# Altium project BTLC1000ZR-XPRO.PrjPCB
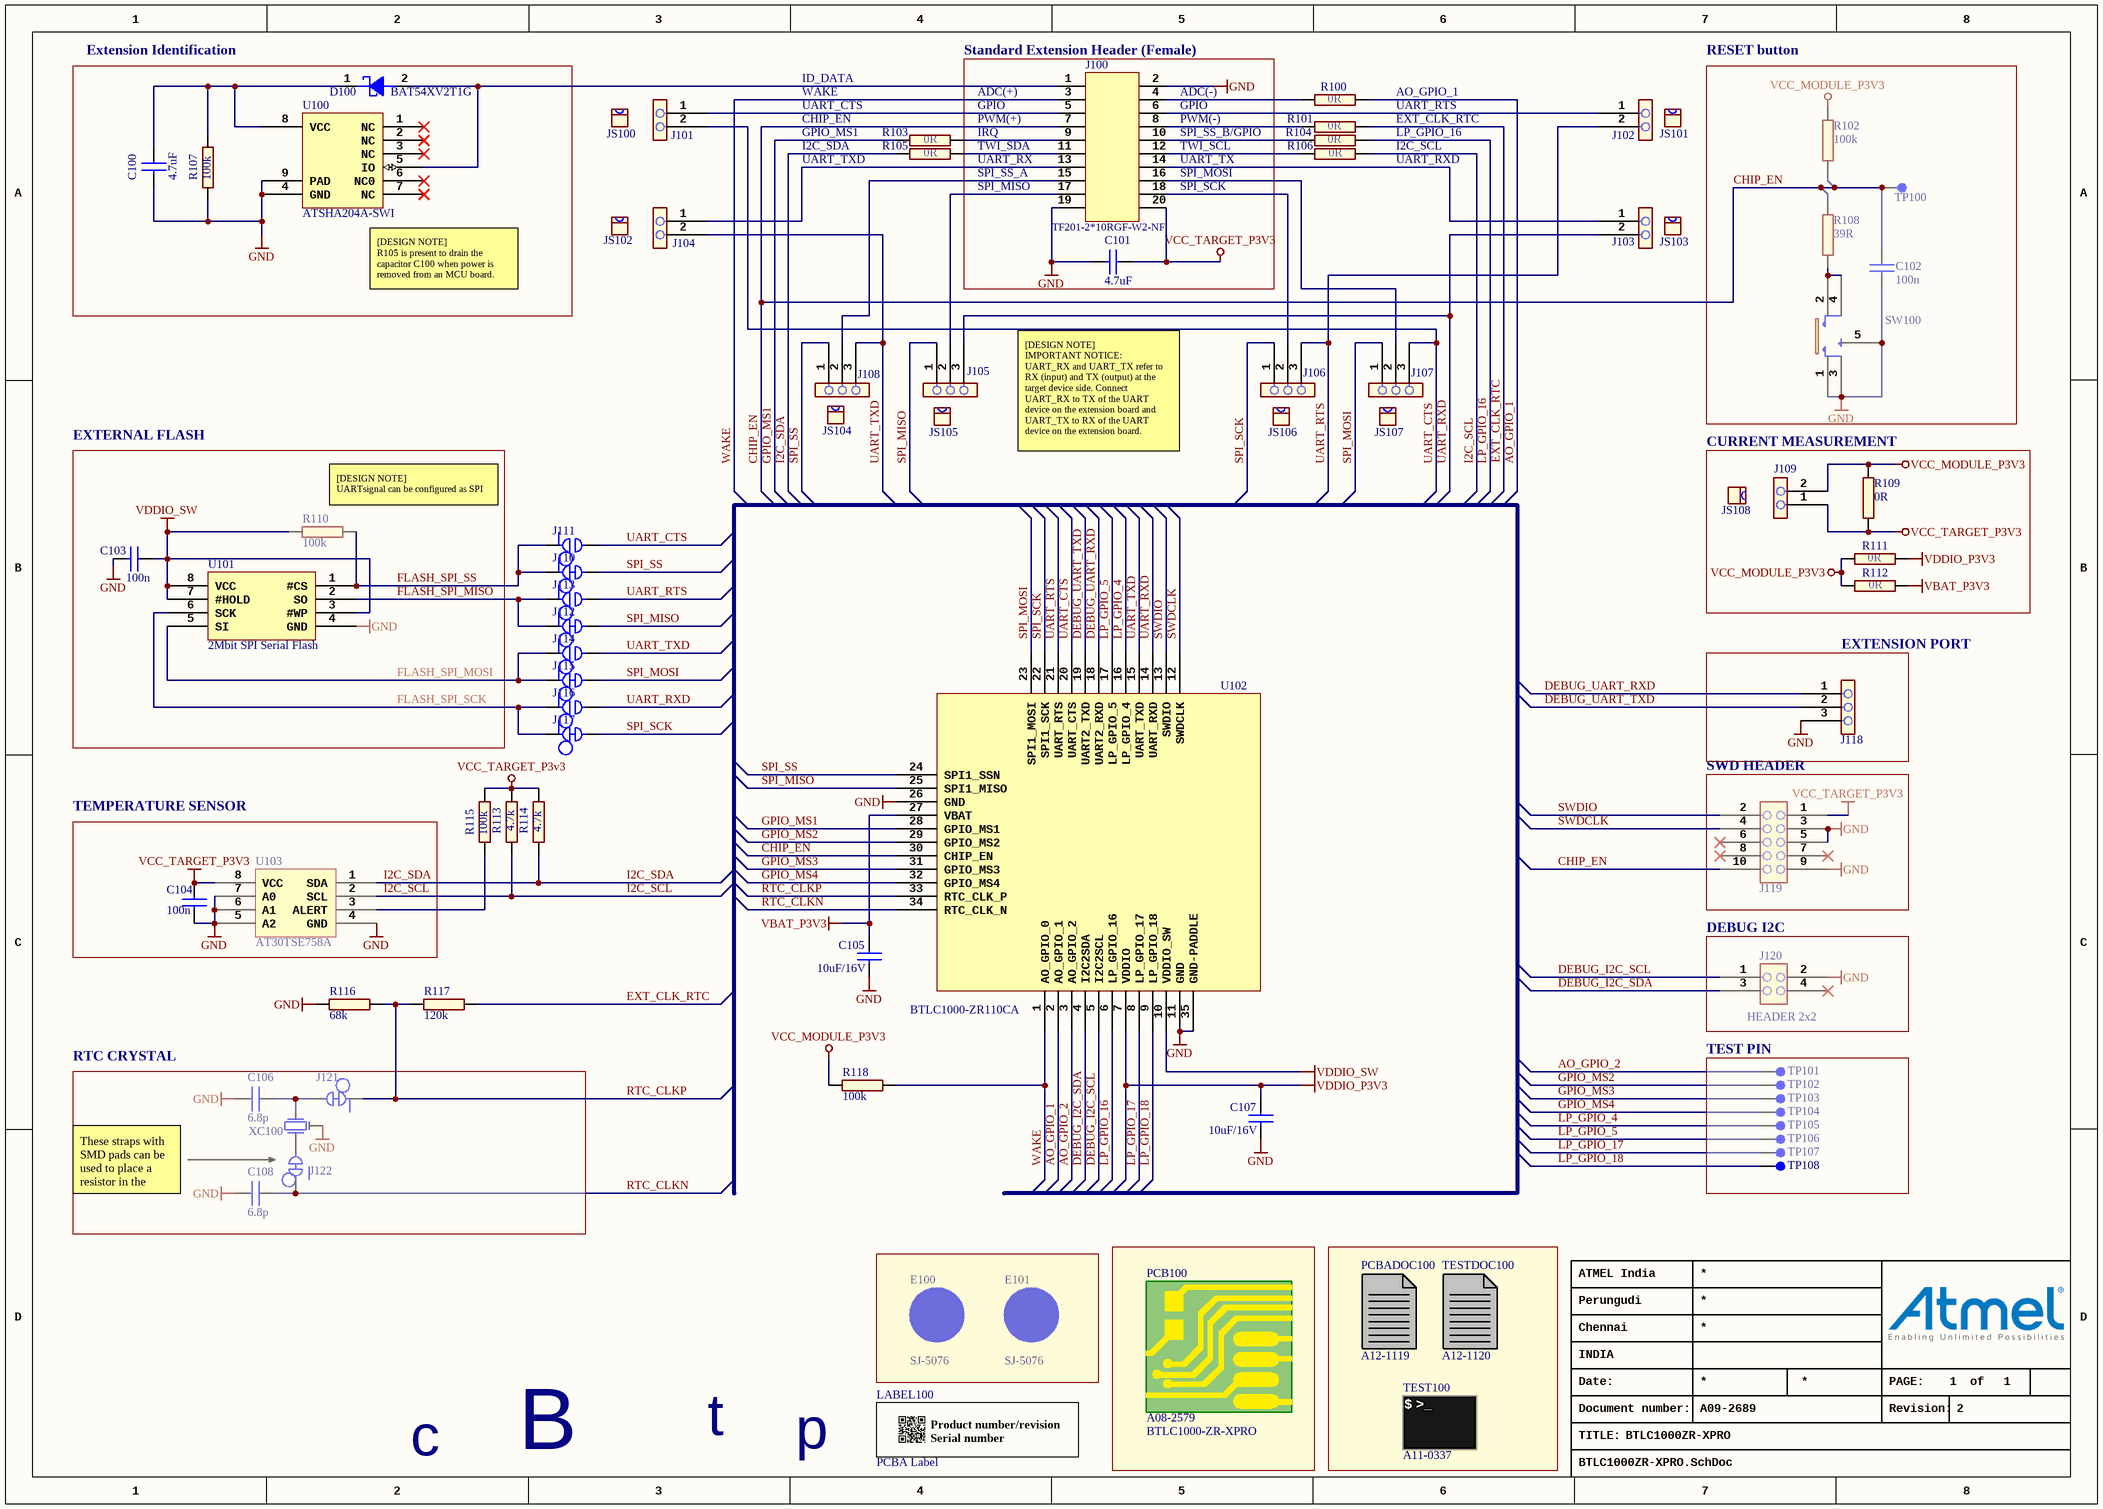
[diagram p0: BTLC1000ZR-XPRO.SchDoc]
1 sheet, 83 parts. Net scope: global (net labels, ports and power ports of the same name join across sheets).
Board file: BTLC1000ZR-XPRO.PcbDoc

## Sheet BTLC1000ZR-XPRO.SchDoc: BTLC1000ZR-XPRO
size A3; Organization: ATMEL India; Address1: Perungudi; Address2: Chennai; Address3: INDIA; DocumentNumber: A09-2689; Revision: 2; SheetNumber: 1; SheetTotal: 1; PageSetup: Record=PageOptions¦CenterHorizontal=True¦CenterVertical=True¦PrintScale=0.68¦XCorrection=1.00¦YCorrection=1.00¦PrintKind=1¦BorderSize=5000000¦LeftOffset=0¦BottomOffset=0¦Orientation=2¦PaperLength=1000¦PaperWidth=1000¦Scale=100¦PaperSource=7¦PrintQuality=-4¦MediaType=1¦DitherType=10¦PaperKind=A3 (297 x 420 mm)¦PrintScaleMode=1

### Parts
C100  value 4.7uF  [AP1-00001]  (hidden comment: Recommended by Escatec. No datasheet available yet.)
C101  value 4.7uF  [AP1-00001]  (hidden comment: Recommended by Escatec. No datasheet available yet.)
C102  100n  [AP1-00053]
C103  value 100n  [AP1-00001]  (hidden comment: CAP-NONPOL)
C104  value 100n  [AP1-00001]  (hidden comment: CAP-NONPOL)
C105  value 10uF/16V  [AP1-00039]  (hidden comment: Close to Pin22(VDDIO)of U101)
C106  value 6.8p  [AP1-00001]  (hidden comment: CAP-NONPOL)
C107  value 10uF/16V  [AP1-00039]  (hidden comment: Close to Pin22(VDDIO)of U101)
C108  value 6.8p  [AP1-00001]  (hidden comment: CAP-NONPOL)
D100  value BAT54XV2T1G  [AP4-00036]  (hidden comment: Farnell# 1615809)
E100  value SJ-5076  [AP8-00192]
E101  value SJ-5076  [AP8-00192]
J100  value TF201-2*10RGF-W2-NF  [AP8-00621]
J101  (no value)  [AP8-00733]
J102  (no value)  [AP8-00733]
J103  (no value)  [AP8-00733]
J104  (no value)  [AP8-00733]
J105  Same as A08-1614 but with 1mm hole for optimal reflow soldering (no misalignment of the component)  [AP8-00745]  (value not drawn)
J106  Same as A08-1614 but with 1mm hole for optimal reflow soldering (no misalignment of the component)  [AP8-00745]  (value not drawn)
J107  Same as A08-1614 but with 1mm hole for optimal reflow soldering (no misalignment of the component)  [AP8-00745]  (value not drawn)
J108  Same as A08-1614 but with 1mm hole for optimal reflow soldering (no misalignment of the component)  [AP8-00745]  (value not drawn)
J109  (no value)  [AP8-00733]
J110  SMD-STRAP_CLOSED  [AP8-00595]  (value not drawn)  (net tie, no BOM)
J111  SMD-STRAP_OPEN  [AP8-00596]  (value not drawn)  (no BOM)
J112  SMD-STRAP_CLOSED  [AP8-00595]  (value not drawn)  (net tie, no BOM)
J113  SMD-STRAP_OPEN  [AP8-00596]  (value not drawn)  (no BOM)
J114  SMD-STRAP_OPEN  [AP8-00596]  (value not drawn)  (no BOM)
J115  SMD-STRAP_CLOSED  [AP8-00595]  (value not drawn)  (net tie, no BOM)
J116  SMD-STRAP_OPEN  [AP8-00596]  (value not drawn)  (no BOM)
J117  SMD-STRAP_CLOSED  [AP8-00595]  (value not drawn)  (net tie, no BOM)
J118  Same as A08-1614 but with 1mm hole for optimal reflow soldering (no misalignment of the component)  [AP8-00745]  (value not drawn)
J119  HEADER 2x5  [AP8-00257]  (value not drawn)
J120  HEADER 2x2  [AP8-00179]
J121  (no value)  [AP9-00044]  (net tie, no BOM)
J122  (no value)  [AP9-00044]  (net tie, no BOM)
JS100  To be used by request from ESCATEC  [AP8-00525]  (value not drawn)
JS101  To be used by request from ESCATEC  [AP8-00525]  (value not drawn)
JS102  To be used by request from ESCATEC  [AP8-00525]  (value not drawn)
JS103  To be used by request from ESCATEC  [AP8-00525]  (value not drawn)
JS104  To be used by request from ESCATEC  [AP8-00525]  (value not drawn)
JS105  To be used by request from ESCATEC  [AP8-00525]  (value not drawn)
JS106  To be used by request from ESCATEC  [AP8-00525]  (value not drawn)
JS107  To be used by request from ESCATEC  [AP8-00525]  (value not drawn)
JS108  To be used by request from ESCATEC  [AP8-00525]  (value not drawn)
LABEL100  value PCBA Label  [AP8-00317]
PCB100  value BTLC1000-ZR-XPRO  AN: A08-2579  (hidden comment: PCB)  (mechanical)
PCBADOC100  AN: A12-1119  (hidden comment: PCBADOC)  (mechanical)
R100  value 0R  [AP2-00001]  (hidden comment: R2)
R101  value 0R  [AP2-00001]  (hidden comment: R2)
R102  value 100k  [AP2-00000]  (hidden comment: R2)
R103  value 0R  [AP2-00001]  (hidden comment: R2)
R104  value 0R  [AP2-00001]  (hidden comment: R2)
R105  value 0R  [AP2-00001]  (hidden comment: R2)
R106  value 0R  [AP2-00001]  (hidden comment: R2)
R107  value 100k  [AP2-00000]
R108  value 39R  [AP2-00000]  (hidden comment: R2)
R109  value 0R  [AP2-00001]  (hidden comment: R2)
R110  value 100k  [AP2-00000]  (hidden comment: R2)
R111  value 0R  [AP2-00001]  (hidden comment: R2)
R112  value 0R  [AP2-00001]  (hidden comment: R2)
R113  value 4.7k  [AP2-00000]  (hidden comment: R2)
R114  value 4.7k  [AP2-00000]  (hidden comment: R2)
R115  value 100k  [AP2-00000]  (hidden comment: R2)
R116  value 68k  [AP2-00001]  (hidden comment: R2)
R117  value 120k  [AP2-00001]  (hidden comment: R2)
R118  value 100k  [AP2-00001]  (hidden comment: R2)
SW100  PUSHBUTTON2  [AP8-00274]  (value not drawn)
TEST100  AN: A11-0337  (hidden comment: TEST)  (mechanical)
TESTDOC100  AN: A12-1120  (hidden comment: TESTDOC)  (mechanical)
TP100  TESTPOINT  [AP8-00010]  (value not drawn)  (no BOM)
TP101  TESTPOINT  [AP8-00256]  (value not drawn)  (no BOM)
TP102  TESTPOINT  [AP8-00256]  (value not drawn)  (no BOM)
TP103  TESTPOINT  [AP8-00256]  (value not drawn)  (no BOM)
TP104  TESTPOINT  [AP8-00256]  (value not drawn)  (no BOM)
TP105  TESTPOINT  [AP8-00256]  (value not drawn)  (no BOM)
TP106  TESTPOINT  [AP8-00256]  (value not drawn)  (no BOM)
TP107  TESTPOINT  [AP8-00256]  (value not drawn)  (no BOM)
TP108  TESTPOINT  [AP8-00256]  (value not drawn)  (no BOM)
U100  ATSHA204A-SWI  [AP6-00409]
U101  value 2Mbit SPI Serial Flash  [AP6-00000]  (hidden comment: IS25LD020-JNLE)
U102  value BTLC1000-ZR110CA  [AP9-00156]  (hidden comment: BTLC1000-ZR-XPRO)
U103  value AT30TSE758A  [AP6-00186]  (hidden comment: AT30TSx75x)
XC100  Farnell order no:1539364  [AP7-00044]  (value not drawn)

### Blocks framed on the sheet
Extension Identification: C100 D100 R107 U100
Standard Extension Header (Female): C101 J100
RESET button: C102 R102 R108 SW100 TP100
EXTERNAL FLASH: C103 R110 U101
CURRENT MEASUREMENT: J109 JS108 R109 R111 R112
EXTENSION PORT: J118
SWD HEADER: J119
TEMPERATURE SENSOR: C104 U103
DEBUG I2C: J120
RTC CRYSTAL: C106 C108 J121 J122 XC100
TEST PIN: TP101-TP108

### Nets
GND: C100.2 C101.2 C102.2 C103.2 C104.2 C105.2 C106.2 C107.2 C108.2 J100.2 J100.19 J118.3 J119.3 J119.5 J119.9 J120.2 R107.1 R116.1 SW100.1 SW100.3 SW100.5(GND) U100.4(GND) U100.9(PAD) U101.4(GND) U102.11(GND) U102.26(GND) U102.35(GND-PADDLE) U103.4(GND) U103.5(A2) U103.6(A1) U103.7(A0) U103.9(GND) XC100.3
VBAT_P3V3: C105.1 R112.1 U102.27(VBAT)
VCC_MODULE_P3V3: J109.2 R102.1 R109.2 R111.2 R112.2 R118.1
VCC_TARGET_P3V3: C101.1 C104.1 J100.20 J109.1 J119.1 R109.1 R113.1 R114.2 R115.1 U103.8(VCC)
VDDIO_P3V3: C107.1 R111.1 U102.7(VDDIO)
VDDIO_SW: C103.1 R110.2 U101.3(#WP) U101.7(#HOLD) U101.8(VCC) U102.10(VDDIO_SW)
AO_GPIO_1: R100.2 U102.2(AO_GPIO_1)
AO_GPIO_2: TP101.1 U102.3(AO_GPIO_2)
CHIP_EN: C102.1 J100.7 J119.10 R102.2 R108.1 TP100.1 U102.30(CHIP_EN)
DEBUG_I2C_SCL: J120.1 U102.5(I2C2SCL)
DEBUG_I2C_SDA: J120.3 U102.4(I2C2SDA)
DEBUG_UART_RXD: J118.1 U102.18(UART2_RXD)
DEBUG_UART_TXD: J118.2 U102.19(UART2_TXD)
EXT_CLK_RTC: R101.2 R117.2
FLASH_SPI_MISO: J112.1 J113.1 U101.2(SO)
FLASH_SPI_MOSI: J114.1 J115.1 U101.5(SI)
FLASH_SPI_SCK: J116.1 J117.1 U101.6(SCK)
FLASH_SPI_SS: J110.1 J111.1 R110.1 U101.1(#CS)
GPIO_MS1: R103.1 U102.28(GPIO_MS1)
GPIO_MS2: TP102.1 U102.29(GPIO_MS2)
GPIO_MS3: TP103.1 U102.31(GPIO_MS3)
GPIO_MS4: TP104.1 U102.32(GPIO_MS4)
I2C_SCL: R106.2 R113.2 U103.2(SCL)
I2C_SDA: R105.1 R114.1 U103.1(SDA)
LP_GPIO_4: TP105.1 U102.16(LP_GPIO_4)
LP_GPIO_5: TP106.1 U102.17(LP_GPIO_5)
LP_GPIO_16: R104.2 U102.6(LP_GPIO_16)
LP_GPIO_17: TP107.1 U102.8(LP_GPIO_17)
LP_GPIO_18: TP108.1 U102.9(LP_GPIO_18)
RTC_CLKN: C108.1 J122.1 U102.34(RTC_CLK_N)
RTC_CLKP: J121.1 R116.2 R117.1 U102.33(RTC_CLK_P)
SPI_MISO: J105.1 J112.2 U102.25(SPI1_MISO)
SPI_MOSI: J107.1 J115.2 U102.23(SPI1_MOSI)
SPI_SCK: J106.1 J117.2 U102.22(SPI1_SCK)
SPI_SS: J108.1 J110.2 U102.24(SPI1_SSN)
SWDCLK: J119.4 U102.12(SWDCLK)
SWDIO: J119.2 U102.13(SWDIO)
UART_CTS: J101.2 J107.3 J111.2 U102.20(UART_CTS)
UART_RTS: J102.2 J106.3 J113.2 U102.21(UART_RTS)
UART_RXD: J103.2 J105.3 J116.2 U102.14(UART_RXD)
UART_TXD: J104.2 J108.3 J114.2 U102.15(UART_TXD)
WAKE: J100.3 R118.2 U102.1(AO_GPIO_0)
NetC100_1: C100.1 D100.1(CATHODE) R107.2 U100.8(VCC)
NetC106_1: C106.1 J121.2 XC100.2
NetD100_2: D100.2(ANODE) J100.1 U100.5(IO)
NetJ100_4: J100.4 R100.1
NetJ100_5: J100.5 J101.1
NetJ100_6: J100.6 J102.1
NetJ100_8: J100.8 R101.1
NetJ100_9: J100.9 R103.2
NetJ100_10: J100.10 R104.1
NetJ100_11: J100.11 R105.2
NetJ100_12: J100.12 R106.1
NetJ100_13: J100.13 J104.1
NetJ100_14: J100.14 J103.1
NetJ100_15: J100.15 J108.2
NetJ100_16: J100.16 J107.2
NetJ100_17: J100.17 J105.2
NetJ100_18: J100.18 J106.2
NetJ122_2: J122.2 XC100.1
NetR108_2: R108.2 SW100.2 SW100.4
NetR115_2: R115.2 U103.3(ALERT)

Not connected (* = marked no-connect by the designer): E100 1(FIDUCIAL); E101 1(FIDUCIAL); J119 6* 7* 8*; J120 4*; U100 1(NC)* 2(NC)* 3(NC)* 6(NC0)* 7(NC)*

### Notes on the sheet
- ID_DATA
- WAKE
- UART_CTS
- ADC(+)
- GPIO
- (near J100) GPIO
- (near J100) ADC(-)
- AO_GPIO_1
- UART_RTS
- CHIP_EN
- GPIO_MS1
- I2C_SDA
- UART_TXD
- TWI_SDA
- UART_RX
- SPI_SS_A
- IRQ
- PWM(+)
- (near J100) PWM(-)
- (near J100) TWI_SCL
- (near J100) UART_TX
- (near J100) SPI_MOSI
- SPI_SS_B/GPIO
- EXT_CLK_RTC
- LP_GPIO_16
- I2C_SCL
- UART_RXD
- SPI_MISO
- (near J100) SPI_SCK
- (near U100) [DESIGN NOTE]
  R105 is present to drain the capacitor C100 when power is removed from an MCU board.
- [DESIGN NOTE]
  IMPORTANT NOTICE:
  UART_RX and UART_TX refer to RX (input) and TX (output) at the target device side. Connect UART_RX to TX of the UART device on the extension board and UART_TX to RX of the UART device on the extension board.
- (near R110) [DESIGN NOTE]
  UARTsignal can be configured as SPI
- These straps with SMD pads can be used to place a resistor in the XOUT signal in order to measure the oscillator allowance.
  By default these straps are closed and nothing is mounted on the pads.
- t
- p
- c
- B

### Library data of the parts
C100 C101 = A01-0347: Ceramic capacitor, SMD 0402, X5R, 6.3V, +/-20% (de33687); PartGroup: Capacitors,Ceramic,SMD 0402; Manufacturer: Murata; MPN: GRM155R60J475ME87D; Tolerance: +-20%; TemperatureRange: -55°C to +85°C; ComponentStatus: 'Active (verified)'
C102-C104 = A01-0246: Ceramic capacitor, SMD 0402, X7R, 16V, +/-10%; PartGroup: Capacitors,Ceramic,SMD 0402; Manufacturer: Kemet; MPN: C0402C104K4RACTU; TemperatureRange: -55 - +125 deg C; ComponentStatus: 'Active (verified)'
C105 C107 = A01-0491: Ceramic capacitor, SMD 0603, X5R, 16V, 10UF ± 20% (High Density); PartGroup: Capacitors,Ceramic,SMD 0603; Manufacturer: Taiyo Yuden; MPN: EMK107BBJ106MA-T; Tolerance: ­± 20%; TemperatureRange: -55°C to +85°C; ComponentStatus: 'Active (verified)'
C106 C108 = A01-0013: Ceramic capacitor, SMD 0402, NP0, 50V, +/-5%; PartGroup: Capacitors,Ceramic,SMD 0402; TemperatureRange: -55 - +125 deg C; ComponentStatus: 'Active (verified)'
D100 = A04-0049: Schottky diode, If:200mA, Vf:0.35V, Vrrm:30V, SOD-523; PartGroup: Diodes,Schottky; Manufacturer: ON Semiconductor; TemperatureRange: -55°C to +125°C; ComponentStatus: 'Active (verified)'
E100 E101 = A08-0053: 2.8mm adhesive feet,diam 8.0mm; PartGroup: Mechanical devices,Mounting accessories; Manufacturer: 3M; ComponentStatus: 'Active (verified)'
J100 = A08-1512: 2x10, female pin header receptable, right-angled, 2.54mm pitch, THM, Pin In Paste; PartGroup: Mechanical devices,Connectors,Pin header receptacle; MPN: F201-2*10RGF-W2-NF; Manufacturer: Pro-data International Corp; ComponentStatus: 'Active (verified)'
J101-J104 J109 = A08-1754: 1x2 pin header, 2.54mm pitch, Pin-in-Paste THM; PartGroup: Mechanical devices,Connectors,Pin headers; Manufacturer: SAMTEC; Value: HMTSW-102-23-F-S-237; TemperatureRange: - 55 deg C to + 125 deg C; ComponentStatus: 'Active (verified)'
J105-J108 J118 = A08-1799: 1x3 pin header, 2.54mm pitch, Pin-in-Paste THM, 1mm hole; PartGroup: Mechanical devices,Connectors,Pin headers; Manufacturer: SAMTEC; Value: HMTSW-103-23-F-S-237; ComponentStatus: 'Active (verified)'
J110 J112 J115 J117 = A08-1454: Closed Link 0402; PartGroup: Mechanical devices,PCB implemented components; ComponentStatus: 'Active (verified)'
J111 J113 J114 J116 = A08-1455: Open Link 0402; PartGroup: Mechanical devices,PCB implemented components; ComponentStatus: 'New (not verified)'
J119 = A08-0385: 2x5 pin header, 1.27mm pitch, THM; PartGroup: Mechanical devices,Connectors,Pin headers; Manufacturer: Garry; MPN: 176-2-010-0-T-XS0-0730; Value: PIN HEADER 2x5; ComponentStatus: 'Active (verified)'
J120 = A08-0115: 2x2 pin header, 2.54 mm pitch, Pin-in-Paste THM; PartGroup: Mechanical devices,Connectors,Pin headers; Manufacturer: Freber; Value: CD0750142X2; ComponentStatus: 'Active (verified)'
J121 J122 = A09-0783: Default closed SMD strap, 0603 size; PartGroup: Mechanical devices,PCB implemented components; Value: SMD-STRAP_0603_CLOSED; ComponentStatus: 'Active (verified)'
JS100-JS108 = A08-0543: Jumper cap for 2.54mm pinheader; PartGroup: Mechanical devices,Mounting accessories,Other; Manufacturer: SAMTEC; Value: SNT-100-BK-G; ComponentStatus: 'Active (verified)'
LABEL100 = A09-0611: PCBA identification label PP Top White Gloss; PartGroup: Mechanical devices,Packaging materials,Printed Labels; Manufacturer: ACT Logimark AS; MPN: 505462; ComponentStatus: 'Active (verified)'
PCB100 = A08-2579: BTLC1000-ZR-XPRO; PartGroup: Mechanical devices,Printed circuit boards; ComponentStatus: 'New (not verified)'
PCBADOC100 = A12-1119: BTLC1000-ZR-XPRO PCBA documentation; PartGroup: Documentation,PCBA Documents,Atmel; ComponentStatus: 'New (not verified)'
R100 R101 R103-R106 R109 R111 R112 = A02-0001: Thick film resistor, SMD 0603, 1/10W, 1%; PartGroup: Resistors,SMD,0603 1%; Manufacturer: Panasonic; MPN: ERJ-3GEY0R00V; ComponentStatus: 'Active (verified)'
R102 R107 R110 R115 = A02-0260: Thick film resistor, SMD 0402, 1/16W, 1%; PartGroup: Resistors,SMD,0402 1%; TemperatureRange: -55ï¿½ to +125ï¿½C; ComponentStatus: 'Active (verified)'
R108 = A02-0178: Thick film resistor, SMD 0402, 1/16W, 1%; PartGroup: Resistors,SMD,0402 1%; TemperatureRange: -55 - +125 deg C; ComponentStatus: 'Active (verified)'
R113 R114 = A02-0228: Thick film resistor, SMD 0402, 1/16W, 1%; PartGroup: Resistors,SMD,0402 1%; TemperatureRange: -55ï¿½ to +125ï¿½C; ComponentStatus: 'Active (verified)'
R116 = A02-0118: Thick film resistor, SMD 0603, 1/10W, 1%; PartGroup: Resistors,SMD,0603 1%; ComponentStatus: 'Active (verified)'
R117 = A02-0124: Thick film resistor, SMD 0603, 1/10W, 1%; PartGroup: Resistors,SMD,0603 1%; ComponentStatus: 'Active (verified)'
R118 = A02-0122: Thick film resistor, SMD 0603, 1/10W, 1%; PartGroup: Resistors,SMD,0603 1%; Manufacturer: Panasonic; MPN: ERJ-3EKF1003V; ComponentStatus: 'Active (verified)'
SW100 = A08-0420: Microminiature Tact Switch for SMT; PartGroup: Mechanical devices,Switches,SMD; Manufacturer: ITT cannon; Value: KMR221G; ComponentStatus: 'Active (verified)'
TEST100 = A11-0337: BTLC1000-ZR-XPRO Test software; PartGroup: Software,Test software,RF; ComponentStatus: 'New (not verified)'
TESTDOC100 = A12-1120: BTLC1000-ZR-XPRO Test Instruction; PartGroup: Documentation,Procedures,Test Instructions; ComponentStatus: 'New (not verified)'
TP100 = A08-0004: Single SMD testpad; PartGroup: Mechanical devices,Connectors,Test points; ComponentStatus: 'Active (verified)'
TP101-TP108 = A09-0290: Hole for user grid with 1.27 mm pitch, 1x1 mm pad; PartGroup: Mechanical devices,PCB implemented components,PCB Screw Hole components; Value: Hole 0.65 mm; ComponentStatus: 'Active (verified)'
U100 = A06-1276: ATSHA204 with 1-wire interface and UDFN8 package; PartGroup: Integrated Circuits,Special function,Encryption; Manufacturer: ATMEL; MPN: ATSHA204A-MAHCZ-T; ComponentStatus: 'Active (verified)'
U101 = A06-1302: 2 Mbit SPI Serial Flash upto 80MHz; PartGroup: Integrated Circuits,Memory,FLASH; Manufacturer: ISSI; ComponentStatus: 'Active (verified)'
U102 = A06-1404: Bluetooth module, 34pin WITH chip Antenna; PartGroup: Integrated Circuits,MCU, MPU, DSP,Other; Manufacturer: Atmel Lake Forest; MPN: ATBTLC1000-ZR110CA; ComponentStatus: 'Active (verified)'
U103 = A06-1300: SINGLE DIGITAL TEMPERATURE SENSOR W/ SERIAL EEPROM, UDFN8; PartGroup: Integrated Circuits,Sensors; Manufacturer: ATMEL; MPN: AT30TSE758A-MA8-T; ComponentStatus: 'New (not verified)'
XC100 = A07-0052: 32k768 crystal, +-20ppm, CL=7pF, max ESR 60kOhm, SMD; PartGroup: Frequency devices,Crystals,SMD; Manufacturer: Micro Crystal; MPN: MS1V-T1K 32.768kHz 7pF +/-20PPM TA; Value: 32.768kHz +/-20PPM 7pF  SMD; Tolerance: +/- 20 PPM; TemperatureRange: -40 /+85; ComponentStatus: 'Active (verified)'

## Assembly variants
Default_assembly: all parts fitted
BTLC1000ZR-XPRO: not fitted C102 C103 C106 C108 D100 J101 J102 J105 J106 J120 J121 J122 JS100 JS101 JS104 JS105 R100 R101 R102 R104 R106 R107 R108 R109 R110 R114 R115 R116 SW100 U101
BTLC1000ZR-XPRO-Proto: not fitted C102 C103 C106 C108 D100 R100 R101 R102 R104 R106 R107 R108 R114 R115 R116 SW100 U101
